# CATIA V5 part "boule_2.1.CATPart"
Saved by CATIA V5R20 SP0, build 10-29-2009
Part number: boule_2.1
Bounding box of the stored display mesh (mm): x 2784.952 to 2880.778, y 81.522 to 181.499, z 1056.306 to 1153.961
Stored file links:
  D:\thinkmotion-MPB\Dropbox\MMS_GR3\CFAO_2010_bfoltzer\CFAO_bfoltzer\boule_2.1.CATPart
  D:\ecole\thinkmotion\Eolienne.CATProduct
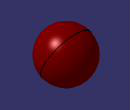
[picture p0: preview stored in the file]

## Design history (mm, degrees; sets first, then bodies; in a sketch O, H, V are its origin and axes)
External parameters (linked from other documents)
  External.rayon_barre = 20 mm
Set1
  Plane1: linked copy from another document
  Point1 to Point3: linked copy from another document
  Line1: linked copy from another document
  Point4: linked copy from another document
  Plane2: linked copy from another document
  Plane3: linked copy from another document
Body1 (main body)
  Sketch1 on Plane1, origin (0, 247.3378, -2.2107), H (1, 0, 0), V (0, -0.1041, 0.9946)
    arc A1 centre (2830.7782, 1112.2228) radius 50 from (2880.7782, 1112.2228) to (2780.7782, 1112.2228) cw
    point P1 (2830.7782, 1112.2228)
    point P2 (2880.7782, 1112.2228)
    point P3 (2780.7782, 1112.2228)
    reference projected point E1 (2780.7782, 1112.2228) from Point1
    reference projected point E2 (2880.7782, 1112.2228) from Point2
    reference projected point E3 (2830.7782, 1112.2228) from Point3
    coincidence: P3 E1, P2 E2, P1 E3
  Shaft1: profile Sketch1, axis Line1, angle 360
  Sketch2 on {plane type Tangent, Support face of Shaft1 from Sketch1.A1, RefPoint Point4}, origin (2830.7782, 1619.9396, 1209.5438), H (1, 0, 0), V (0, 0.9946, 0.1041)
    point P1 (0, -1491.3308)
    reference projected point E1 (0, -1491.3308) from Point4
    coincidence: E1 P1
  Hole1: placed by Sketch2, at (2830.7782, 136.7177, 1054.2364) direction (0, -0.1041, 0.9946), diameter 40 {= External.rayon_barre *2}, up to Plane2
  Sketch3 on {plane type Tangent, Support face of Shaft1 from Sketch1.A1, RefPoint Point1}, origin (2780.7782, 9.9847, 1109.9551), H (0, 1, 0), V (0, 0, 1)
    point P1 (121.526, -5.9906)
    reference projected point E1 (121.526, -5.9906) from Point1
    coincidence: E1 P1
  Hole2: placed by Sketch3, at (2780.7782, 131.5107, 1103.9645) direction (1, 0, 0), diameter 40 {= External.rayon_barre *2}, up to Plane3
